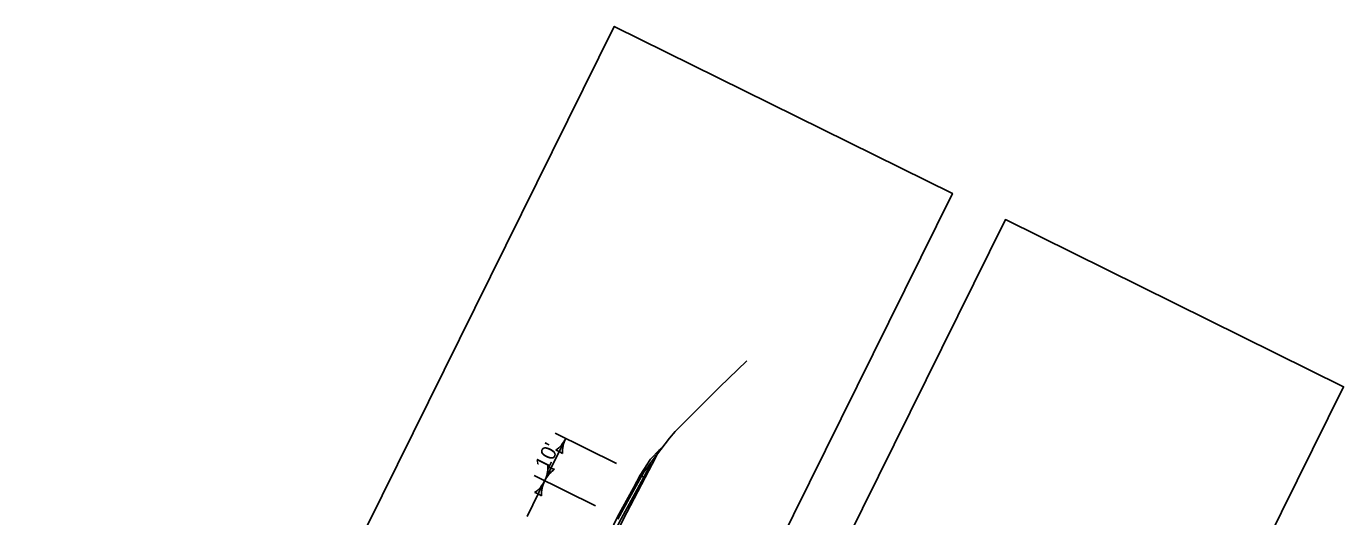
# Model space of a CAD drawing. Extents: x 14097936 to 14128734, y 8632000 to 8683104.
# Drawn here: x 14118892 to 14120004, y 8672470 to 8672885 of the extents above; entities that cross this region are included whole.
import ezdxf

# ---------------------------------------------------------------- set-up
doc = ezdxf.new("R2010")
doc.units = 0
for name, color, linetype in [('dsnCellElements', 7, 'Continuous'), ('dsnTextOverlapEven', 7, 'Continuous'), ('TC_PCCPavement', 7, 'Continuous'), ('TC_ShoulderEarthFill', 7, 'Continuous'), ('TC_Subbase', 7, 'Continuous'), ('Terrain', 7, 'Continuous')]:
    doc.layers.add(name, color=color, linetype=linetype)

# ---------------------------------------------------------------- blocks, each defined once
blk = doc.blocks.new('LT')
at = {"layer": 'dsnCellElements'}
for centre, radius, start, end in [((-3.56, 0), 1.64, 342.2666, 17.7333), ((0, 4.25), 4.25, 241.9275, 270), ((0, -4.25), 4.25, 90, 118.0725)]:
    blk.add_arc(centre, radius, start, end, dxfattribs=at)

msp = doc.modelspace()

# ---------------------------------------------------------------- linework, layer by layer
at = {"layer": 'dsnTextOverlapEven'}
for p, q in [((14119390.3, 8672515.2), (14119338.5, 8672540.7)), ((14119329.7, 8672500.4), (14119347.5, 8672536.3)), ((14119314.9, 8672470.4), (14119329.7, 8672500.4)), ((14119372.6, 8672479.3), (14119320.8, 8672504.9))]:
    msp.add_line(p, q, dxfattribs=at)
for points in [[(14118892.1, 8671880.5), (14119388.5, 8672884.5), (14119674, 8672743.3), (14119177.6, 8671739.3)], [(14119222.4, 8671717.2), (14119718.8, 8672721.2), (14120004.4, 8672580), (14119508, 8671576)]]:
    msp.add_lwpolyline(points, close=True, dxfattribs=at)
at = {"layer": 'TC_PCCPavement'}
msp.add_line((14119410.5, 8672505.2), (14119413.5, 8672503.7), dxfattribs=at)
for points in [[(14119305, 8672288.8), (14119308.6, 8672296.8), (14119320.7, 8672322.6), (14119332.9, 8672348.4), (14119349.4, 8672383.7), (14119356.6, 8672398.8), (14119363.9, 8672413.9), (14119370.1, 8672427), (14119384.9, 8672457.1), (14119391.3, 8672470), (14119404.7, 8672494.6), (14119410.5, 8672505.2)], [(14119308, 8672287.3), (14119311.6, 8672295.3), (14119323.7, 8672321.1), (14119335.8, 8672347), (14119352.4, 8672382.2), (14119359.6, 8672397.3), (14119366.8, 8672412.5), (14119373.1, 8672425.5), (14119387.9, 8672455.6), (14119394.3, 8672468.5), (14119407.7, 8672493.1), (14119413.5, 8672503.7)]]:
    msp.add_lwpolyline(points, dxfattribs=at)
at = {"layer": 'TC_ShoulderEarthFill'}
msp.add_line((14119420.5, 8672514.7), (14119426.7, 8672526.6), dxfattribs=at)
at = {"layer": 'TC_Subbase'}
for points in [[(14119294.6, 8672253.4), (14119295.3, 8672254.9), (14119306.6, 8672279.7), (14119313.4, 8672294.4), (14119325.5, 8672320.3), (14119333.8, 8672337.9), (14119354.2, 8672381.3), (14119374.9, 8672424.6), (14119396.1, 8672467.7), (14119414.5, 8672503.2), (14119420.5, 8672514.7)], [(14119413.5, 8672503.7), (14119419.2, 8672514.2), (14119420.5, 8672514.7)]]:
    msp.add_lwpolyline(points, dxfattribs=at)
at = {"layer": 'Terrain'}
for points in [[(14119391.6, 8672468.2), (14119401.4, 8672486), (14119411.2, 8672503.9), (14119412.8, 8672506.8), (14119413.4, 8672507.8), (14119420.5, 8672517.5), (14119435.2, 8672536.4), (14119440, 8672542.1), (14119477.3, 8672579.5), (14119500.3, 8672601.8)], [(14119410.5, 8672505.2), (14119419, 8672518.8), (14119426.7, 8672526.6), (14119430.8, 8672530.7)]]:
    msp.add_lwpolyline(points, dxfattribs=at)

# ---------------------------------------------------------------- block references
at = {"layer": 'dsnTextOverlapEven', "yscale": 6.308076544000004}
for p, xscale, rotation in [((14119347.5, 8672536.2), 6.308076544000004, 63.69110745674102), ((14119329.7, 8672500.4), 6.308076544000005, -116.30889254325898), ((14119329.7, 8672500.4), 6.308076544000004, 63.69110745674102)]:
    msp.add_blockref('LT', p, dxfattribs=dict(at, xscale=xscale, rotation=rotation))

# ---------------------------------------------------------------- texts
at = {"layer": 'dsnTextOverlapEven'}
msp.add_text("10'", height=12.8, rotation=63.6911, dxfattribs=at).set_placement((14119332.3, 8672508.4))

doc.saveas('drawing.dxf')
